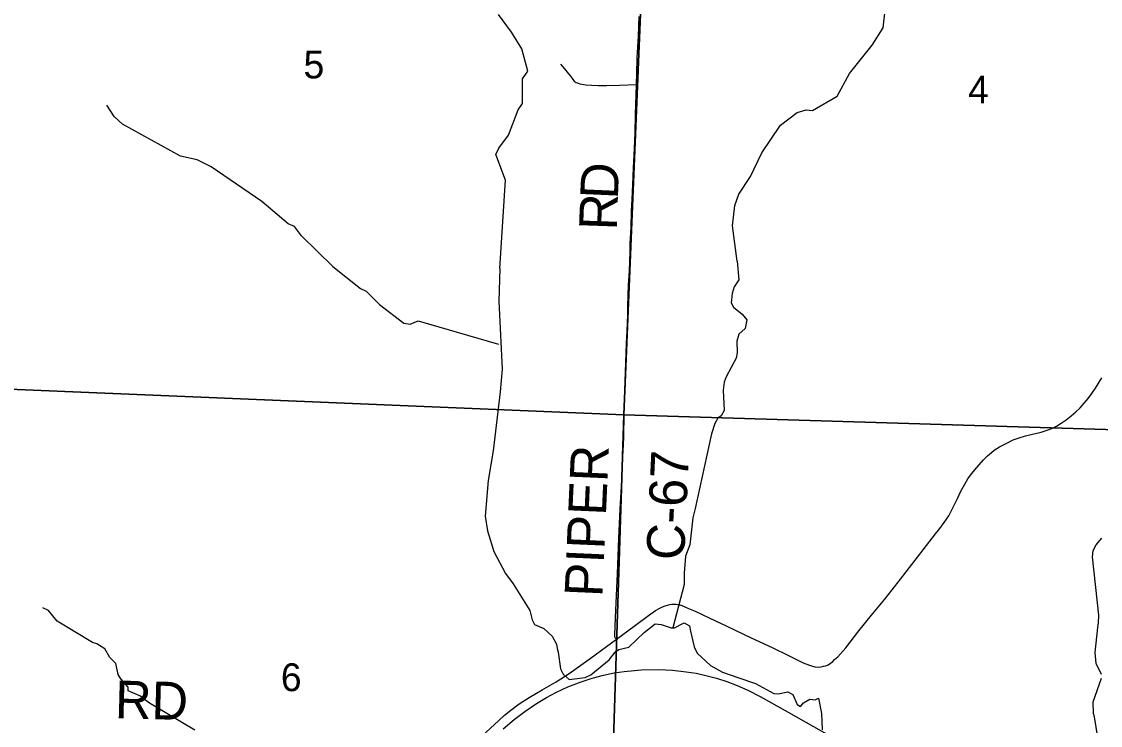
# Model space of a CAD drawing. Extents: x 0 to 34, y 0 to 22.
# Drawn here: x 5.686 to 7.308, y 18.823 to 19.882 of the extents above; entities that cross this region are included whole.
import ezdxf

# ---------------------------------------------------------------- set-up
doc = ezdxf.new("R2010")
doc.units = 0
for name, color, linetype in [('GM_X_County_Road', 7, 'Continuous'), ('GM_X_County_Road_Text', 7, 'Continuous'), ('GM_X_Minor_River', 7, 'Continuous'), ('GM_X_Rail_Line', 7, 'Continuous'), ('GM_X_Section', 7, 'Continuous'), ('GM_X_Section_Text', 7, 'Continuous'), ('GM_X_Township_Road', 7, 'Continuous')]:
    doc.layers.add(name, color=color, linetype=linetype)

msp = doc.modelspace()

# ---------------------------------------------------------------- linework, layer by layer
at = {"layer": 'GM_X_County_Road'}
for points in [[(6.6105, 19.7877), (6.6111, 19.8042), (6.6118, 19.8271), (6.6134, 19.8601), (6.6144, 19.89)], [(6.5806, 18.953), (6.5788, 18.9554), (6.578, 18.9576), (6.578, 18.9593), (6.5792, 18.986), (6.5821, 19.0516), (6.5843, 19.1053), (6.5862, 19.1487), (6.5877, 19.1741), (6.5885, 19.1926), (6.5893, 19.215), (6.5906, 19.2362), (6.5915, 19.2572), (6.5922, 19.2928), (6.5927, 19.3139), (6.5931, 19.3274), (6.5942, 19.3548), (6.5953, 19.3832), (6.5958, 19.3981), (6.5967, 19.4163), (6.5977, 19.4409), (6.5977, 19.4538), (6.5988, 19.4862), (6.5999, 19.5065), (6.6009, 19.5369), (6.6013, 19.548), (6.6024, 19.573), (6.6033, 19.5971), (6.6041, 19.615), (6.6052, 19.6366), (6.6063, 19.6622), (6.6075, 19.6911), (6.6085, 19.7155), (6.6091, 19.7423), (6.6105, 19.7877)], [(6.5806, 18.953), (6.5883, 18.9586), (6.6091, 18.9743), (6.6285, 18.9888), (6.6392, 18.9961), (6.6449, 18.9995), (6.6498, 19.0018), (6.6538, 19.0034), (6.6573, 19.0045), (6.6609, 19.0052), (6.6637, 19.0056), (6.6673, 19.0059), (6.6701, 19.0056), (6.673, 19.0054), (6.6758, 19.0047), (6.6787, 19.0038), (6.6822, 19.0024), (6.689, 18.9993), (6.6986, 18.9952), (6.7201, 18.9851), (6.7464, 18.9727), (6.783, 18.9553), (6.8144, 18.9407), (6.8391, 18.9286), (6.8524, 18.9219), (6.8614, 18.9176), (6.8705, 18.914), (6.8737, 18.913), (6.879, 18.9115), (6.8838, 18.9112), (6.8884, 18.9115), (6.892, 18.9124), (6.8951, 18.9132), (6.8987, 18.9148), (6.9023, 18.9173), (6.9057, 18.9197), (6.9085, 18.9224), (6.9131, 18.9266), (6.9172, 18.9311), (6.9253, 18.9404), (6.9451, 18.9657), (6.9642, 18.9891), (6.984, 19.0136), (6.9952, 19.0275), (7.0076, 19.0434), (7.0414, 19.0877), (7.0603, 19.1115), (7.0669, 19.1197), (7.0734, 19.1288), (7.08, 19.1389), (7.0854, 19.1488), (7.0934, 19.1647), (7.0984, 19.1756), (7.1042, 19.1865), (7.1089, 19.1943), (7.1143, 19.2018), (7.1221, 19.2114), (7.1324, 19.223), (7.1384, 19.2288), (7.1445, 19.2342), (7.1484, 19.2373), (7.1564, 19.2423), (7.1666, 19.2477), (7.1769, 19.253), (7.186, 19.2562), (7.1953, 19.259), (7.2061, 19.2616), (7.2188, 19.2646), (7.2281, 19.2677), (7.235, 19.2703), (7.2419, 19.2738), (7.2493, 19.2781), (7.2567, 19.2831), (7.2642, 19.2892), (7.2711, 19.2951), (7.2777, 19.3013), (7.2835, 19.3081), (7.2896, 19.3153), (7.2953, 19.3227), (7.3005, 19.3305), (7.3103, 19.3464)], [(6.3605, 18.792), (6.3657, 18.7958), (6.3788, 18.8078), (6.403, 18.8302), (6.4124, 18.8389), (6.4218, 18.8466), (6.434, 18.8559), (6.4492, 18.8656), (6.4686, 18.8772), (6.4896, 18.8891), (6.5092, 18.9015), (6.541, 18.9239), (6.5806, 18.953)]]:
    msp.add_lwpolyline(points, dxfattribs=at)
at = {"layer": 'GM_X_Minor_River'}
for points in [[(6.7622, 19.522), (6.7551, 19.575), (6.7587, 19.6057), (6.7646, 19.6228), (6.7819, 19.649), (6.799, 19.6848), (6.8272, 19.7262), (6.852, 19.7454), (6.8656, 19.7492), (6.8754, 19.7482), (6.9124, 19.77), (6.9311, 19.8039), (6.9649, 19.8469), (6.9813, 19.8728), (6.9874, 19.9262)], [(6.4049, 19.5106), (6.4135, 19.6438), (6.3989, 19.682), (6.4034, 19.6919), (6.4184, 19.7113), (6.4325, 19.7496), (6.4393, 19.7592), (6.4391, 19.7963), (6.4473, 19.8077), (6.4384, 19.8414), (6.4227, 19.8663), (6.4033, 19.893)], [(6.1541, 19.5136), (6.1069, 19.5599), (6.0962, 19.5738), (6.0867, 19.5779), (6.0472, 19.6117), (5.9709, 19.6639), (5.95, 19.674), (5.925, 19.6795), (5.8377, 19.7281), (5.8252, 19.7394), (5.8145, 19.7564)], [(6.1541, 19.5136), (6.1958, 19.4805), (6.2041, 19.4768), (6.2243, 19.4564), (6.2607, 19.4285), (6.2702, 19.427), (6.2826, 19.432), (6.4031, 19.397)], [(6.7622, 19.522), (6.7643, 19.4938), (6.7575, 19.4831), (6.7545, 19.4729), (6.7531, 19.4592), (6.7565, 19.4524), (6.7694, 19.4422), (6.7767, 19.4335), (6.7741, 19.4206), (6.7643, 19.4122), (6.7613, 19.4016), (6.7618, 19.3841), (6.7603, 19.3757), (6.7453, 19.3479), (6.7423, 19.3396), (6.7409, 19.3278), (6.7425, 19.2974), (6.738, 19.2891), (6.7331, 19.2856), (6.7286, 19.2776), (6.7234, 19.262), (6.6986, 19.1499), (6.6953, 19.1355), (6.6906, 19.0952), (6.6842, 19.0781), (6.6825, 19.0527), (6.6822, 19.0356), (6.6655, 18.9702)], [(6.4049, 19.5106), (6.4035, 19.4615), (6.4086, 19.3591), (6.4054, 19.3253), (6.3952, 19.2364), (6.3875, 19.1919), (6.3832, 19.138), (6.3867, 19.116), (6.396, 19.0853), (6.4139, 19.052), (6.4253, 19.0365), (6.4501, 18.9964), (6.4536, 18.9824), (6.4574, 18.9752), (6.4714, 18.9692), (6.484, 18.9575), (6.4901, 18.9458), (6.4913, 18.9389), (6.4928, 18.9336), (6.4963, 18.9086), (6.5005, 18.9006), (6.5096, 18.8923), (6.5335, 18.8955), (6.5418, 18.8997), (6.5696, 18.9223), (6.5783, 18.9337), (6.5843, 18.9375), (6.5991, 18.941), (6.6224, 18.9632), (6.6386, 18.9762), (6.6477, 18.9754), (6.6625, 18.9702), (6.6678, 18.9702), (6.6821, 18.9779), (6.6904, 18.9734), (6.692, 18.9654), (6.6974, 18.9415), (6.702, 18.9321), (6.7221, 18.9136), (6.74, 18.9034), (6.7646, 18.8952), (6.7896, 18.8866), (6.8169, 18.8716), (6.8237, 18.8712), (6.8381, 18.874), (6.8457, 18.8702), (6.8522, 18.8551), (6.8571, 18.8517), (6.8616, 18.8574), (6.8714, 18.8631), (6.8794, 18.8617), (6.8843, 18.8644), (6.8889, 18.8416), (6.8898, 18.8169)], [(7.3097, 18.9), (7.3016, 18.9167), (7.3, 18.933), (7.304, 18.9706), (7.3051, 18.9778), (7.3058, 18.9892), (7.2963, 19.0772), (7.2974, 19.0867), (7.3019, 19.0951), (7.3105, 19.105)], [(5.9468, 18.8161), (5.8785, 18.8567), (5.8637, 18.868), (5.8462, 18.8755), (5.8462, 18.8808), (5.8352, 18.8933), (5.8313, 18.9001), (5.8279, 18.9164), (5.8187, 18.9258), (5.8111, 18.9387), (5.799, 18.9462), (5.7929, 18.9481), (5.7398, 18.9801), (5.7268, 18.9963), (5.7181, 19.0001)], [(7.1596, 18.6419), (7.1668, 18.6506), (7.1667, 18.6582), (7.1739, 18.6681), (7.1923, 18.6815), (7.2127, 18.6911), (7.249, 18.7038), (7.2637, 18.7176), (7.2846, 18.7587), (7.2982, 18.78), (7.3011, 18.7876), (7.3041, 18.8051), (7.2994, 18.8362), (7.2979, 18.8415), (7.297, 18.859), (7.3097, 18.8947)]]:
    msp.add_lwpolyline(points, dxfattribs=at)
at = {"layer": 'GM_X_Rail_Line'}
msp.add_lwpolyline([(6.4104, 18.8181), (6.4268, 18.8324), (6.4428, 18.8445), (6.4602, 18.8563), (6.4753, 18.8654), (6.4905, 18.8737), (6.5073, 18.8814), (6.5272, 18.889), (6.5438, 18.8944), (6.5612, 18.8992), (6.5768, 18.9023), (6.5923, 18.9047), (6.6077, 18.9062), (6.6176, 18.907), (6.6439, 18.9078), (6.6648, 18.9068), (6.6853, 18.9043), (6.7004, 18.9019), (6.715, 18.8986), (6.731, 18.8946), (6.7464, 18.8894), (6.7622, 18.8834), (6.7779, 18.8763), (6.7965, 18.8668), (6.8389, 18.8435), (7.0174, 18.7422)], dxfattribs=at)
at = {"layer": 'GM_X_Section'}
for points in [[(5.6562, 20.3612), (6.6348, 20.3279), (6.5918, 19.2905), (5.6189, 19.331), (5.6549, 20.3275)], [(6.6348, 20.3279), (7.6587, 20.2884), (7.6132, 19.2594), (6.5918, 19.2905)], [(6.5918, 19.2905), (6.5595, 18.2824), (5.5833, 18.3028), (5.6189, 19.331)], [(6.5918, 19.2905), (7.6132, 19.2594), (7.5782, 18.246), (6.5595, 18.2824)]]:
    msp.add_lwpolyline(points, close=True, dxfattribs=at)
at = {"layer": 'GM_X_Township_Road'}
msp.add_lwpolyline([(6.4963, 19.8183), (6.5024, 19.8113), (6.5084, 19.8038), (6.5117, 19.7996), (6.5149, 19.795), (6.5171, 19.7926), (6.5197, 19.7906), (6.5227, 19.7893), (6.5256, 19.7884), (6.5285, 19.7878), (6.5343, 19.7871), (6.5434, 19.7863), (6.5536, 19.7858), (6.5653, 19.7858), (6.585, 19.7865), (6.6105, 19.7877)], dxfattribs=at)

# ---------------------------------------------------------------- texts
at = {"layer": 'GM_X_County_Road_Text'}
for s, height, rotation, p in [('D', 0.0568, 87.4565, (6.5825, 19.6142)), ('R', 0.0568, 87.9895, (6.5809, 19.5677)), ('PIPER', 0.05682, 87.4778, (6.5592, 19.016)), ('C-67', 0.05682, 87.2923, (6.682, 19.0711)), ('RD', 0.05682, 358.5128, (5.826, 18.8343))]:
    msp.add_text(s, height=height, rotation=rotation, dxfattribs=at).set_placement(p)
at = {"layer": 'GM_X_Section_Text'}
for s, p in [('5', (6.11, 19.7967)), ('4', (7.1092, 19.759)), ('6', (6.0759, 18.875))]:
    msp.add_text(s, height=0.0419, rotation=0, dxfattribs=at).set_placement(p)

doc.saveas('drawing.dxf')
